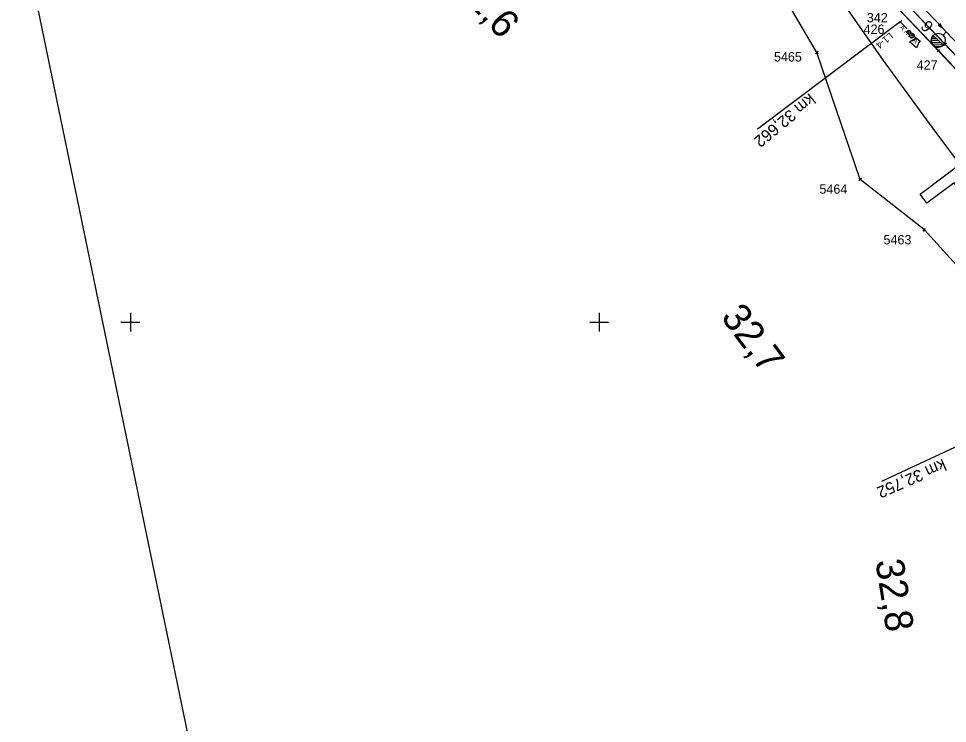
# Model space of a CAD drawing. Extents: x -804166 to -803706, y -1151030 to -1150147.
# Drawn here: x -804123.8 to -803925.7, y -1150585.6 to -1150435.2 of the extents above; entities that cross this region are included whole.
import ezdxf

# ---------------------------------------------------------------- set-up
doc = ezdxf.new("R2010")
doc.units = 0
for name, color, linetype in [('0381KM032-037P - Vrstva 1', 7, 'Continuous'), ('0381KM032-037P - Vrstva 2', 7, 'Continuous'), ('0381KM032-037P - Vrstva 27', 7, 'Continuous'), ('0381KM032-037P - Vrstva 33', 7, 'Continuous'), ('0381KM032-037P - Vrstva 4', 7, 'Continuous'), ('0381KM032-037P - Vrstva 55', 7, 'Continuous'), ('0381KM032-037P - Vrstva 6', 7, 'Continuous'), ('0381KM032-037P - Vrstva 7', 7, 'Continuous'), ('DZ_CD - CD', 7, 'Continuous'), ('DZ_CD - CD_čísla', 7, 'Continuous'), ('formát', 7, 'Continuous'), ('krizky_1000 - Vrstva 1', 7, 'Continuous'), ('szdc - hran DP', 7, 'Continuous'), ('szdc - szdc_cislo', 7, 'Continuous'), ('szdc - szdc_krizek', 7, 'Continuous'), ('VB - VB', 7, 'Continuous'), ('VB - VB_cislo', 7, 'Continuous'), ('VB - VB_krizek', 7, 'Continuous')]:
    doc.layers.add(name, color=color, linetype=linetype)

msp = doc.modelspace()

# ---------------------------------------------------------------- linework, layer by layer
at = {"layer": '0381KM032-037P - Vrstva 1'}
msp.add_line((-803925.98, -1150438.01), (-803923.25, -1150440.92), dxfattribs=at)
for points in [[(-803975.62, -1150392.3), (-803939.47, -1150444.12), (-803928.27, -1150459.42), (-803914.53, -1150477.73)], [(-803942.6, -1150419.03), (-803934.7, -1150428.88), (-803926.85, -1150437.12), (-803925.98, -1150438.01)], [(-803943.83, -1150420.17), (-803934.7, -1150428.88), (-803926.85, -1150437.12), (-803925.98, -1150438.01)]]:
    msp.add_lwpolyline(points, dxfattribs=at)
at = {"layer": '0381KM032-037P - Vrstva 2'}
for p, q in [((-803928.99, -1150439.08), (-803928.5, -1150439.07)), ((-803926.61, -1150440.86), (-803928.79, -1150438.8)), ((-803928.79, -1150438.8), (-803926.61, -1150440.86)), ((-803925.98, -1150438.01), (-803926.67, -1150438.74)), ((-803929.19, -1150439.89), (-803927.68, -1150439.84)), ((-803929.15, -1150439.49), (-803928.09, -1150439.46)), ((-803929.12, -1150440.29), (-803927.27, -1150440.23)), ((-803928.93, -1150440.68), (-803926.86, -1150440.62)), ((-803928.53, -1150441.07), (-803926.79, -1150441.02))]:
    msp.add_line(p, q, dxfattribs=at)
for points in [[(-803943.83, -1150420.17), (-803934.7, -1150428.88), (-803926.85, -1150437.12), (-803925.98, -1150438.01)], [(-803927.71, -1150436.6), (-803926.85, -1150437.12), (-803927.34, -1150436.24)]]:
    msp.add_lwpolyline(points, dxfattribs=at)
msp.add_circle((-803927.7, -1150439.83), 1.5, dxfattribs=at)
msp.add_arc((-803927.7, -1150439.83), 1.5, 136.6555, 316.6555, dxfattribs=at)
at = {"layer": '0381KM032-037P - Vrstva 27'}
msp.add_line((-803933.41, -1150438.82), (-803933.31, -1150438.82), dxfattribs=at)
msp.add_circle((-803933.36, -1150438.82), 0.5, dxfattribs=at)
at = {"layer": '0381KM032-037P - Vrstva 33'}
for p, q in [((-803934.19, -1150437.82), (-803934.13, -1150438.5)), ((-803933.79, -1150437.78), (-803933.73, -1150438.47)), ((-803931.5, -1150440.19), (-803933.64, -1150438.38)), ((-803933.84, -1150440.17), (-803932.49, -1150439.35)), ((-803932.31, -1150441.46), (-803933.84, -1150440.17)), ((-803931.73, -1150439.99), (-803932.31, -1150441.46))]:
    msp.add_line(p, q, dxfattribs=at)
msp.add_circle((-803933.96, -1150438.14), 0.401, dxfattribs=at)
msp.add_circle((-803933.96, -1150438.14), 0.401, dxfattribs=at)
at = {"layer": '0381KM032-037P - Vrstva 4'}
msp.add_line((-803875.88, -1150504.25), (-803939.78, -1150533.94), dxfattribs=at)
at = {"layer": '0381KM032-037P - Vrstva 55'}
msp.add_lwpolyline([(-803914.71, -1150478.01), (-803919.01, -1150472.26), (-803921.41, -1150474.2), (-803924.33, -1150470.27), (-803930.11, -1150474.6), (-803931.57, -1150472.66), (-803925.79, -1150468.33), (-803920.83, -1150464.56), (-803917.63, -1150468.64), (-803916.3, -1150467.69), (-803915.12, -1150469.35), (-803916.46, -1150470.34), (-803904.84, -1150485.91), (-803905.5, -1150486.41)], dxfattribs=at)
at = {"layer": '0381KM032-037P - Vrstva 6'}
for p, q in [((-803935.82, -1150435.93), (-803966.23, -1150458.78)), ((-803935.46, -1150435.58), (-803936.18, -1150436.28)), ((-803934.43, -1150437.34), (-803935.82, -1150435.93))]:
    msp.add_line(p, q, dxfattribs=at)
at = {"layer": 'DZ_CD - CD'}
for p, q in [((-803913.4, -1150454.32), (-803936.11, -1150430.3)), ((-803937.53, -1150431.71), (-803914.93, -1150455.61))]:
    msp.add_line(p, q, dxfattribs=at)
at = {"layer": 'formát'}
msp.add_line((-804123.84, -1150413.06), (-804081.38, -1150618.72), dxfattribs=at)
at = {"layer": 'krizky_1000 - Vrstva 1'}
for points in [[(-804100, -1150498), (-804100, -1150502)], [(-804000, -1150498), (-804000, -1150502)], [(-804102, -1150500), (-804098, -1150500)], [(-804002, -1150500), (-803998, -1150500)]]:
    msp.add_lwpolyline(points, dxfattribs=at)
at = {"layer": 'szdc - hran DP'}
for p, q in [((-803953.58, -1150442.45), (-803965.92, -1150421.41)), ((-803944.36, -1150469.51), (-803953.58, -1150442.45)), ((-803930.65, -1150480.27), (-803944.36, -1150469.51)), ((-803915.62, -1150496.95), (-803930.65, -1150480.27))]:
    msp.add_line(p, q, dxfattribs=at)
at = {"layer": 'szdc - szdc_krizek'}
for p, q in [((-803953.32, -1150442.72), (-803953.85, -1150442.19)), ((-803953.85, -1150442.72), (-803953.32, -1150442.19)), ((-803944.09, -1150469.78), (-803944.63, -1150469.25)), ((-803944.63, -1150469.78), (-803944.09, -1150469.25)), ((-803930.39, -1150480.53), (-803930.92, -1150480.01)), ((-803930.92, -1150480.53), (-803930.39, -1150480.01))]:
    msp.add_line(p, q, dxfattribs=at)
at = {"layer": 'VB - VB'}
for p, q in [((-803936.11, -1150430.3), (-803926.23, -1150440.67)), ((-803937.53, -1150431.71), (-803927.68, -1150442.04)), ((-803926.23, -1150440.67), (-803913.4, -1150454.32)), ((-803927.68, -1150442.04), (-803914.93, -1150455.61))]:
    msp.add_line(p, q, dxfattribs=at)
at = {"layer": 'VB - VB_krizek'}
for p, q in [((-803925.96, -1150440.93), (-803926.49, -1150440.4)), ((-803926.49, -1150440.93), (-803925.96, -1150440.4)), ((-803927.42, -1150442.31), (-803927.95, -1150441.78)), ((-803927.95, -1150442.31), (-803927.42, -1150441.78))]:
    msp.add_line(p, q, dxfattribs=at)

# ---------------------------------------------------------------- texts
at = {"layer": '0381KM032-037P - Vrstva 2'}
msp.add_text('9', height=2.5, rotation=311.6555, dxfattribs=at).set_placement((-803931.66, -1150437))
at = {"layer": '0381KM032-037P - Vrstva 4'}
msp.add_text('km 32,752', height=2.5, rotation=203.5952, dxfattribs=at).set_placement((-803926.7, -1150529.09))
at = {"layer": '0381KM032-037P - Vrstva 6'}
for s, height, rotation, p in [('  A A A A ', 1, 314.5182, (-803936.53, -1150436.63)), ('L1-4', 1.5, 219.5182, (-803938.06, -1150438.08)), ('km 32,662', 2.5, 219.5182, (-803955.2, -1150451.01))]:
    msp.add_text(s, height=height, rotation=rotation, dxfattribs=at).set_placement(p)
at = {"layer": '0381KM032-037P - Vrstva 7'}
for s, rotation, p in [('32,6', 311.8828, (-804031.4, -1150428.19)), ('32,7', 306.901, (-803974.22, -1150498.93)), ('32,8', 278.8223, (-803941.12, -1150550.92))]:
    msp.add_text(s, height=6, rotation=rotation, dxfattribs=at).set_placement(p)
at = {"layer": 'DZ_CD - CD_čísla'}
msp.add_text('342', height=2, dxfattribs=at).set_placement((-803942.93, -1150436.01))
at = {"layer": 'szdc - szdc_cislo'}
for s, p in [('5465', (-803962.74, -1150444.36)), ('5464', (-803953.04, -1150472.58)), ('5463', (-803939.37, -1150483.39))]:
    msp.add_text(s, height=2, dxfattribs=at).set_placement(p)
at = {"layer": 'VB - VB_cislo'}
for s, p in [('426', (-803943.63, -1150438.48)), ('427', (-803932.3, -1150446.13))]:
    msp.add_text(s, height=2, dxfattribs=at).set_placement(p)

doc.saveas('drawing.dxf')
